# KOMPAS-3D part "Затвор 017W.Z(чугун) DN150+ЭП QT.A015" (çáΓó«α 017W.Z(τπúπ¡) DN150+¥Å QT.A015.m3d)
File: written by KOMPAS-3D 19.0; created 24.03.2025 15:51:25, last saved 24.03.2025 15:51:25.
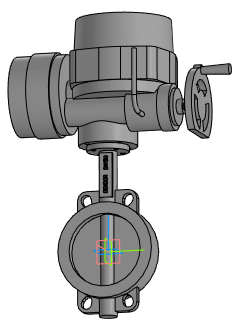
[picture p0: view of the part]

Document properties: Полное имя файла: Затвор 017W.Z(чугун) DN150+ЭП QT.A015.a3d

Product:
- Part/product: Затвор 017W.Z(чугун) DN150+ЭП QT.A015
    Масса: 99.6845

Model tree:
1. Операция без истории:1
